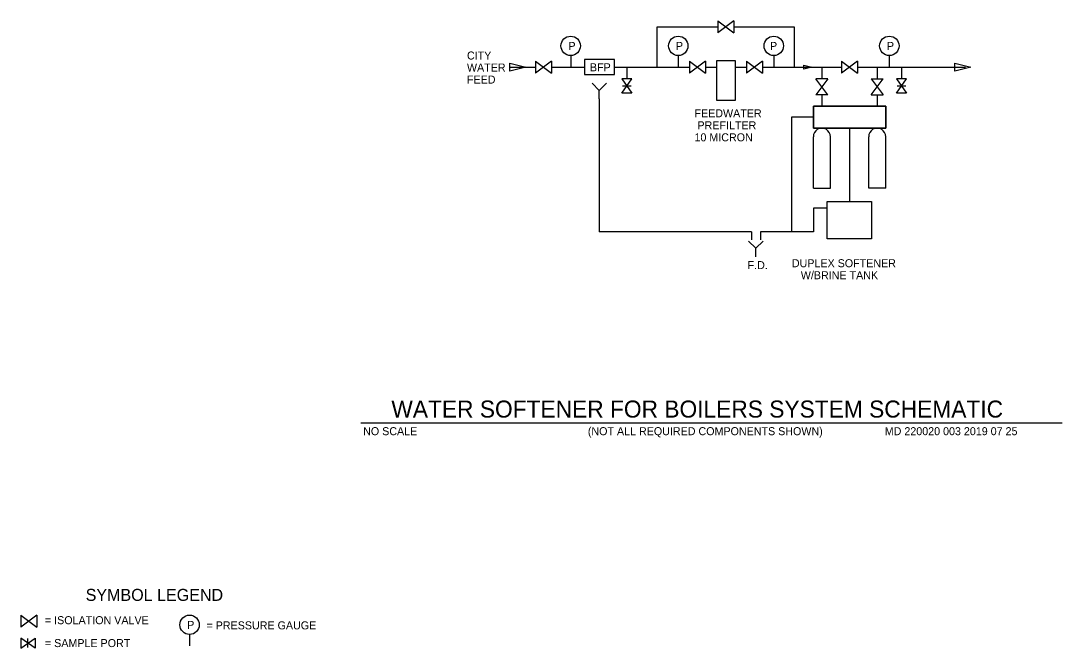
# Model space of a CAD drawing. Extents: x 9936.5 to 10023.2, y 10040.7 to 10093.
import ezdxf

# ---------------------------------------------------------------- set-up
doc = ezdxf.new("R2010")
doc.units = 0
for name, color, linetype in [('G-ANNO-CELL', 7, 'Continuous'), ('G-ANNO-TEXT', 7, 'Continuous'), ('M-STEM-CONP', 7, 'Continuous')]:
    doc.layers.add(name, color=color, linetype=linetype)

msp = doc.modelspace()

# ---------------------------------------------------------------- linework, layer by layer
at = {"layer": 'G-ANNO-CELL'}
msp.add_line((9964.852, 10059.501), (10023.249, 10059.501), dxfattribs=at)
at = {"layer": 'G-ANNO-TEXT'}
for p, q in [((9982.319, 10090.072), (9982.319, 10089.118)), ((9991.278, 10090.072), (9991.278, 10089.118)), ((9999.23, 10090.072), (9999.23, 10089.118)), ((10008.852, 10090.072), (10008.852, 10089.118)), ((9984.699, 10087.162), (9984.095, 10087.766)), ((9984.699, 10087.162), (9985.302, 10087.766)), ((9984.699, 10086.463), (9984.699, 10087.162)), ((9984.699, 10086.463), (9984.699, 10075.383)), ((10002.526, 10084.941), (10000.697, 10084.941)), ((10000.697, 10084.941), (10000.697, 10075.383)), ((10002.526, 10079.019), (10002.526, 10083.318)), ((10003.944, 10079.019), (10003.944, 10083.318)), ((10005.54, 10084.032), (10005.54, 10077.915)), ((10007.135, 10079.019), (10007.135, 10083.318)), ((10008.554, 10079.019), (10008.554, 10083.318)), ((10002.526, 10079.019), (10003.944, 10079.019)), ((10008.554, 10079.019), (10007.135, 10079.019)), ((10003.678, 10077.357), (10002.54, 10077.357)), ((10002.54, 10077.357), (10002.54, 10075.383)), ((9997.363, 10075.383), (9984.699, 10075.383)), ((9997.742, 10074.023), (9997.138, 10074.626)), ((9997.363, 10075.383), (9997.363, 10074.725)), ((9997.742, 10074.023), (9998.345, 10074.626)), ((10002.54, 10075.383), (9998.12, 10075.383)), ((9998.12, 10075.383), (9998.12, 10074.725)), ((9997.742, 10073.324), (9997.742, 10074.023)), ((9936.526, 10043.49), (9936.526, 10042.49)), ((9936.526, 10043.49), (9937.859, 10042.49)), ((9937.859, 10043.49), (9936.526, 10042.49)), ((9937.859, 10043.49), (9937.859, 10042.49)), ((9950.578, 10041.873), (9950.578, 10040.92)), ((9936.526, 10041.569), (9936.526, 10040.736)), ((9936.526, 10040.736), (9937.716, 10041.569)), ((9937.716, 10040.736), (9936.526, 10041.569)), ((9937.121, 10040.802), (9937.121, 10041.533)), ((9937.716, 10041.569), (9937.716, 10040.736))]:
    msp.add_line(p, q, dxfattribs=at)
for points in [[(9994.498, 10089.66), (9996.01, 10089.66), (9996.01, 10086.328), (9994.498, 10086.328)], [(10002.526, 10085.849), (10008.554, 10085.849), (10008.554, 10084.032), (10002.526, 10084.032)], [(10008.554, 10085.849), (10002.526, 10085.849), (10002.526, 10084.032), (10008.554, 10084.032)], [(10003.678, 10077.915), (10007.357, 10077.915), (10007.357, 10074.812), (10003.678, 10074.812)]]:
    msp.add_lwpolyline(points, close=True, dxfattribs=at)
for centre in [(9982.319, 10090.88), (9991.278, 10090.88), (9999.23, 10090.88), (10008.852, 10090.88), (9950.578, 10042.681)]:
    msp.add_circle(centre, 0.808, dxfattribs=at)
for centre, start, end in [((10003.235, 10083.318), 359.99989, 180), ((10007.845, 10083.318), 0, 180.00011)]:
    msp.add_arc(centre, 0.709, start, end, dxfattribs=at)
at = {"layer": 'M-STEM-CONP'}
for p, q in [((9994.564, 10092.962), (9994.564, 10091.962)), ((9994.564, 10092.962), (9995.897, 10091.962)), ((9995.897, 10092.962), (9994.564, 10091.962)), ((9995.897, 10092.962), (9995.897, 10091.962)), ((9989.531, 10089.118), (9989.531, 10092.462)), ((9989.531, 10092.462), (9994.564, 10092.462)), ((9995.897, 10092.462), (10000.93, 10092.462)), ((10000.93, 10092.462), (10000.93, 10089.118)), ((9979.389, 10089.618), (9979.389, 10088.618)), ((9979.389, 10089.618), (9980.722, 10088.618)), ((9980.722, 10089.618), (9979.389, 10088.618)), ((9980.722, 10089.618), (9980.722, 10088.618)), ((9992.212, 10089.618), (9992.212, 10088.618)), ((9992.212, 10089.618), (9993.545, 10088.618)), ((9993.545, 10089.618), (9992.212, 10088.618)), ((9993.545, 10089.618), (9993.545, 10088.618)), ((9996.963, 10089.618), (9996.963, 10088.618)), ((9998.296, 10089.618), (9996.963, 10088.618)), ((9996.963, 10089.618), (9998.296, 10088.618)), ((9998.296, 10089.618), (9998.296, 10088.618)), ((10004.873, 10089.618), (10004.873, 10088.618)), ((10004.873, 10089.618), (10006.206, 10088.618)), ((10006.206, 10089.618), (10004.873, 10088.618)), ((10006.206, 10089.618), (10006.206, 10088.618)), ((9977.258, 10089.118), (9979.389, 10089.118)), ((9980.722, 10089.118), (9983.455, 10089.118)), ((9985.955, 10089.118), (9992.212, 10089.118)), ((9986.996, 10089.107), (9986.996, 10088.143)), ((9993.545, 10089.118), (9994.498, 10089.118)), ((9996.01, 10089.118), (9996.963, 10089.118)), ((9998.296, 10089.118), (10004.873, 10089.118)), ((10003.235, 10089.107), (10003.235, 10088.143)), ((10006.206, 10089.118), (10015.197, 10089.118)), ((10007.845, 10089.107), (10007.845, 10088.143)), ((10009.858, 10089.107), (10009.858, 10088.143)), ((9987.413, 10088.143), (9986.58, 10088.143)), ((9986.58, 10088.143), (9987.413, 10086.953)), ((9986.58, 10086.953), (9987.413, 10088.143)), ((10003.735, 10088.143), (10002.735, 10088.143)), ((10003.735, 10088.143), (10002.735, 10086.81)), ((10003.735, 10086.81), (10002.735, 10088.143)), ((10007.345, 10088.143), (10008.345, 10088.143)), ((10007.345, 10088.143), (10008.345, 10086.81)), ((10007.345, 10086.81), (10008.345, 10088.143)), ((10010.275, 10088.143), (10009.442, 10088.143)), ((10009.442, 10088.143), (10010.275, 10086.953)), ((10009.442, 10086.953), (10010.275, 10088.143)), ((9987.413, 10086.953), (9986.58, 10086.953)), ((9986.631, 10087.548), (9987.361, 10087.548)), ((10003.735, 10086.81), (10002.735, 10086.81)), ((10003.235, 10086.81), (10003.235, 10085.849)), ((10007.345, 10086.81), (10008.345, 10086.81)), ((10007.845, 10086.81), (10007.845, 10085.849)), ((10010.275, 10086.953), (10009.442, 10086.953)), ((10009.508, 10087.548), (10010.238, 10087.548))]:
    msp.add_line(p, q, dxfattribs=at)
for points in [[(9977.262, 10089.452), (9978.596, 10089.118), (9977.262, 10088.785)], [(9985.955, 10089.743), (9983.455, 10089.743), (9983.455, 10088.493), (9985.955, 10088.493)], [(10014.314, 10089.452), (10015.647, 10089.118), (10014.314, 10088.785)], [(10001.729, 10089.285), (10002.396, 10089.118), (10001.729, 10088.952)]]:
    msp.add_lwpolyline(points, close=True, dxfattribs=at)

# ---------------------------------------------------------------- texts
at = {"layer": 'G-ANNO-CELL'}
for s, height, p in [('WATER SOFTENER FOR BOILERS SYSTEM SCHEMATIC', 1.41667, (9967.383, 10059.934)), ('NO SCALE', 0.6667, (9965.033, 10058.466))]:
    msp.add_text(s, height=height, dxfattribs=at).set_placement(p)
at = {"layer": 'G-ANNO-TEXT'}
for s, height, p in [('P', 0.667, (9982.129, 10090.538)), ('P', 0.667, (9991.082, 10090.538)), ('P', 0.667, (10008.656, 10090.538)), ('CITY', 0.6667, (9973.679, 10089.741)), ('WATER', 0.6667, (9973.679, 10088.741)), ('FEED', 0.6667, (9973.679, 10087.741)), ('FEEDWATER', 0.6667, (9992.627, 10084.931)), (' PREFILTER', 0.6667, (9992.627, 10083.931)), ('10 MICRON', 0.6667, (9992.627, 10082.931)), ('F.D.', 0.6667, (9997.051, 10072.292)), ('DUPLEX SOFTENER', 0.66667, (10000.737, 10072.449)), ('   W/BRINE TANK', 0.66667, (10000.737, 10071.449)), ('(NOT ALL REQUIRED COMPONENTS SHOWN)', 0.66667, (9983.746, 10058.466)), ('MD 220020 003 2019 07 25', 0.66667, (10008.473, 10058.466)), ('SYMBOL LEGEND', 1, (9941.927, 10044.672)), ('= ISOLATION VALVE', 0.66667, (9938.534, 10042.732)), ('P', 0.667, (9950.382, 10042.34)), ('= PRESSURE GAUGE', 0.66667, (9951.987, 10042.3)), ('= SAMPLE PORT', 0.66667, (9938.534, 10040.826))]:
    msp.add_text(s, height=height, dxfattribs=at).set_placement(p)
msp.add_text('P', height=0.667, rotation=360, dxfattribs=at).set_placement((9998.92, 10090.538))
at = {"layer": 'M-STEM-CONP'}
msp.add_text('BFP', height=0.6667, dxfattribs=at).set_placement((9983.921, 10088.761))

doc.saveas('drawing.dxf')
